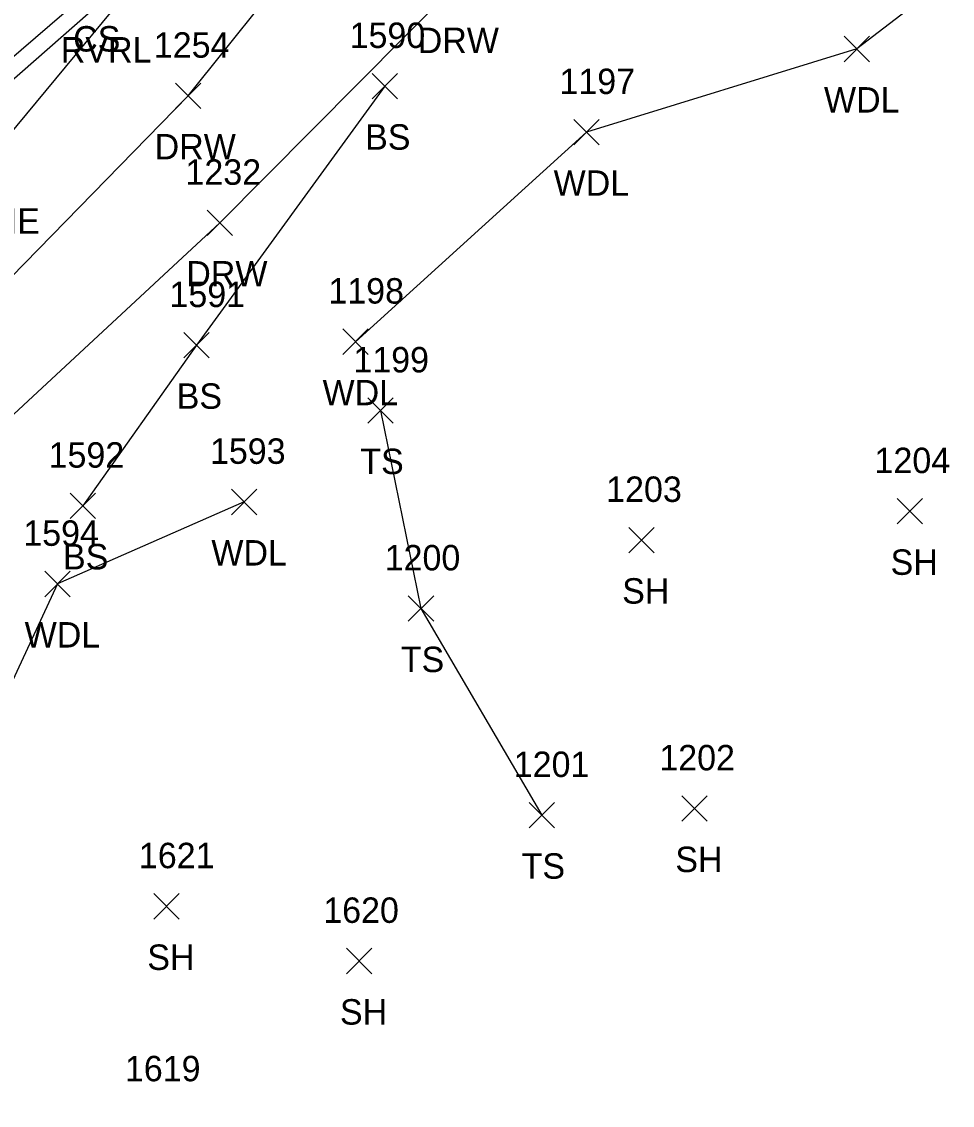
# Model space of a CAD drawing. Extents: x 1621633 to 1624015, y 417863 to 420979.
# Drawn here: x 1621983.5 to 1622056.7, y 417982.6 to 418067.9 of the extents above; entities that cross this region are included whole.
import ezdxf

# ---------------------------------------------------------------- set-up
doc = ezdxf.new("R2010")
doc.units = 0
for name, color, linetype in [('L_A', 7, 'Continuous'), ('L_I', 7, 'Continuous'), ('L_TIC', 7, 'Continuous'), ('LASF', 7, 'Continuous'), ('LAWA', 7, 'Continuous'), ('LAWE', 7, 'Continuous'), ('LELB', 7, 'Continuous'), ('R_A', 7, 'Continuous'), ('R_I', 7, 'Continuous'), ('R_TIC', 7, 'Continuous'), ('RDW', 7, 'Continuous')]:
    doc.layers.add(name, color=color, linetype=linetype)

msp = doc.modelspace()

# ---------------------------------------------------------------- linework, layer by layer
at = {"layer": 'L_TIC'}
for points in [[(1622048.191, 418064.738), (1622050.191, 418066.738)], [(1622050.191, 418064.738), (1622048.191, 418066.738)], [(1622011.075, 418061.817), (1622013.075, 418063.817)], [(1622013.075, 418061.817), (1622011.075, 418063.817)], [(1622026.926, 418058.192), (1622028.926, 418060.192)], [(1622028.926, 418058.192), (1622026.926, 418060.192)], [(1621996.254, 418041.437), (1621998.254, 418043.437)], [(1621998.254, 418041.437), (1621996.254, 418043.437)], [(1622008.751, 418041.713), (1622010.751, 418043.713)], [(1622010.751, 418041.713), (1622008.751, 418043.713)], [(1622010.727, 418036.299), (1622012.727, 418038.299)], [(1622012.727, 418036.299), (1622010.727, 418038.299)], [(1621987.311, 418028.806), (1621989.311, 418030.806)], [(1621989.311, 418028.806), (1621987.311, 418030.806)], [(1622000.004, 418029.107), (1622002.004, 418031.107)], [(1622002.004, 418029.107), (1622000.004, 418031.107)], [(1622052.357, 418028.376), (1622054.357, 418030.376)], [(1622054.357, 418028.376), (1622052.357, 418030.376)], [(1622031.248, 418026.112), (1622033.248, 418028.112)], [(1622033.248, 418026.112), (1622031.248, 418028.112)], [(1621985.32, 418022.658), (1621987.32, 418024.658)], [(1621987.32, 418022.658), (1621985.32, 418024.658)], [(1622013.911, 418020.725), (1622015.911, 418022.725)], [(1622015.911, 418020.725), (1622013.911, 418022.725)], [(1622035.427, 418004.996), (1622037.427, 418006.996)], [(1622037.427, 418004.996), (1622035.427, 418006.996)], [(1622023.415, 418004.475), (1622025.415, 418006.475)], [(1622025.415, 418004.475), (1622023.415, 418006.475)], [(1621993.895, 417997.3), (1621995.895, 417999.3)], [(1621995.895, 417997.3), (1621993.895, 417999.3)], [(1622009.05, 417992.999), (1622011.05, 417994.999)], [(1622011.05, 417992.999), (1622009.05, 417994.999)]]:
    msp.add_lwpolyline(points, dxfattribs=at)
at = {"layer": 'LASF'}
msp.add_lwpolyline([(1622002.675, 418093.219), (1621997.296, 418076.86), (1621980.179, 418056.204), (1621954.756, 418039.139), (1621928.826, 418024.949), (1621900.016, 418015.523), (1621882.357, 418011.741)], dxfattribs=at)
at = {"layer": 'LAWA'}
for points in [[(1622320.95, 418130.743), (1622294.184, 418128.87), (1622284.857, 418124.812), (1622280.855, 418118.535), (1622268.545, 418119.809), (1622252.021, 418123.74), (1622232.124, 418123.259), (1622206.962, 418121.212), (1622178.234, 418118.308), (1622148.867, 418114.963), (1622127.557, 418112.544), (1622101.307, 418110.446), (1622091.62, 418108.262), (1622075.892, 418086.213), (1622049.191, 418065.738), (1622027.926, 418059.192), (1622009.751, 418042.713)], [(1622001.004, 418030.107), (1621986.32, 418023.658), (1621975.506, 418000.432), (1621955.157, 417983.756), (1621932.198, 417971.155), (1621904.748, 417967.466), (1621879.49, 417952.716), (1621860.189, 417941.587), (1621844.309, 417921.469), (1621821.118, 417913.626), (1621798.12, 417906.333), (1621768.531, 417901.526), (1621742.571, 417889.758), (1621727.863, 417881.174)]]:
    msp.add_lwpolyline(points, dxfattribs=at)
at = {"layer": 'LAWE'}
msp.add_lwpolyline([(1621694.469, 417944.857), (1621713.846, 417956.733), (1621742.172, 417966.049), (1621760.532, 417975.456), (1621777.237, 417983.398), (1621792.696, 417991.301), (1621817.095, 418001.163), (1621844.467, 418008.037), (1621871.363, 418013.308), (1621897.422, 418019.495), (1621922.912, 418028.804), (1621945.859, 418038.978), (1621969.359, 418051.535), (1621990.012, 418069.674), (1621996.064, 418084.217), (1621996.533, 418092.287)], dxfattribs=at)
at = {"layer": 'LELB'}
for points in [[(1621694.018, 417945.604), (1621713.058, 417958.392), (1621741.418, 417968.002), (1621759.92, 417977.729), (1621776.332, 417984.988), (1621792.046, 417992.579), (1621816.284, 418002.68), (1621844.088, 418009.589), (1621869.849, 418015.692), (1621896.837, 418021.913), (1621921.805, 418030.632), (1621944.897, 418041.057), (1621968.773, 418053.066), (1621989.111, 418070.538), (1621994.262, 418084.512), (1621994.522, 418092.07)], [(1622012.075, 418062.817), (1621997.254, 418042.437), (1621988.311, 418029.806)], [(1622011.727, 418037.299), (1622014.911, 418021.725), (1622024.415, 418005.475)]]:
    msp.add_lwpolyline(points, dxfattribs=at)
at = {"layer": 'R_TIC'}
for points in [[(1621995.59, 418061.054), (1621997.59, 418063.054)], [(1621997.59, 418061.054), (1621995.59, 418063.054)], [(1621998.079, 418051.056), (1622000.079, 418053.056)], [(1622000.079, 418051.056), (1621998.079, 418053.056)]]:
    msp.add_lwpolyline(points, dxfattribs=at)
at = {"layer": 'RDW'}
for points in [[(1622068.286, 418109.151), (1622048.314, 418092.064), (1622031.513, 418075.622), (1622017.283, 418070.416), (1621999.079, 418052.056), (1621978.461, 418032.933), (1621951.05, 418013.179), (1621921.756, 418000.239), (1621894.363, 417990.232), (1621865.95, 417979.751)], [(1621869.66, 417990.005), (1621898.189, 417999.842), (1621925.17, 418010.412), (1621952.262, 418024.445), (1621976.225, 418041.199), (1621996.59, 418062.054), (1622014.164, 418083.988), (1622019.779, 418092.569), (1622014.506, 418097.249)]]:
    msp.add_lwpolyline(points, dxfattribs=at)

# ---------------------------------------------------------------- texts
at = {"layer": 'L_A'}
for s, p in [('CS', (1621987.552, 418065.538)), ('RVRL', (1621986.579, 418064.674)), ('WDL', (1622046.608, 418060.738)), ('BS', (1622010.516, 418057.817)), ('WDL', (1622025.343, 418054.192)), ('STONE', (1621975.723, 418051.204)), ('BS', (1621995.695, 418037.437)), ('WDL', (1622007.168, 418037.713)), ('TS', (1622010.136, 418032.299)), ('WDL', (1621998.421, 418025.107)), ('BS', (1621986.752, 418024.806)), ('SH', (1622051.845, 418024.376)), ('SH', (1622030.736, 418022.112)), ('WDL', (1621983.737, 418018.658)), ('TS', (1622013.32, 418016.725)), ('TS', (1622022.825, 418000.475)), ('SH', (1622034.916, 418000.996)), ('SH', (1621993.384, 417993.3)), ('SH', (1622008.538, 417988.999))]:
    msp.add_text(s, height=2, dxfattribs=at).set_placement(p)
at = {"layer": 'L_I'}
for s, p in [('1590', (1622009.295, 418065.817)), ('1197', (1622025.8, 418062.192)), ('1591', (1621995.128, 418045.437)), ('1198', (1622007.625, 418045.713)), ('1199', (1622009.593, 418040.299)), ('1592', (1621985.618, 418032.806)), ('1593', (1621998.311, 418033.107)), ('1204', (1622050.585, 418032.376)), ('1203', (1622029.476, 418030.112)), ('1594', (1621983.627, 418026.658)), ('1200', (1622012.053, 418024.725)), ('1202', (1622033.656, 418008.996)), ('1201', (1622022.21, 418008.475)), ('1621', (1621992.722, 418001.3)), ('1620', (1622007.223, 417996.999)), ('1619', (1621991.622, 417984.541))]:
    msp.add_text(s, height=2, dxfattribs=at).set_placement(p)
at = {"layer": 'R_A'}
for p in [(1622014.653, 418065.416), (1621993.961, 418057.054), (1621996.449, 418047.056)]:
    msp.add_text('DRW', height=2, dxfattribs=at).set_placement(p)
at = {"layer": 'R_I'}
for s, p in [('1254', (1621993.898, 418065.054)), ('1232', (1621996.386, 418055.056))]:
    msp.add_text(s, height=2, dxfattribs=at).set_placement(p)

doc.saveas('drawing.dxf')
